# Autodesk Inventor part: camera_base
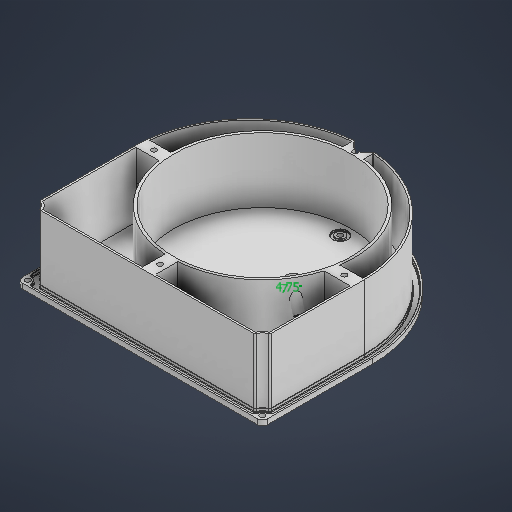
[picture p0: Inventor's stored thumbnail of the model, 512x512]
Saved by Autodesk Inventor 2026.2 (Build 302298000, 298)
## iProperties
Created: 2026-02
Part Number: camera_base
Material: Generic
Document SubType Name: Modeling
Designer: Tathagata Sikdar
Density: 1 g/cm^3
Appearance: Default
Author: Tathagata Sikdar
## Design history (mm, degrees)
sketch "Sketch1"
  geometry: L1 (0, -60.044)-(52, 30.022); L2 (52, 30.022)-(-52, 30.022); L3 (-52, 30.022)-(0, -60.044); L4 (-26, -15.011)-(52, 30.022); L5 (0, -60.044)-(0, 30.022); L6 (94.574, 10.03)-(94.574, 90.574); L7 (-94.574, 10.03)-(-94.574, 90.574); L8 (90.574, 94.574)-(-90.574, 94.574); L9 (93.154, 10.03)-(93.154, 84.168); L10 (84.168, 93.154)-(-84.168, 93.154); L11 (-93.154, 84.168)-(-93.154, 10.03); L12 (88.994, 10.03)-(88.994, 82.391); L13 (82.391, 88.994)-(-82.391, 88.994); L14 (-88.994, 82.391)-(-88.994, 10.03); L15 (-90.574, 90.574)-(-94.574, 94.574); L16 (0, 0)-(90.574, 90.574); L17 (82.089, 87.574)-(-82.089, 87.574); L18 (-87.574, 82.089)-(-87.574, 10.03); L19 (87.574, 10.03)-(87.574, 82.089); L20 (80.971, 87.574)-(56.971, 87.574); L21 (56.971, 87.574)-(56.971, 41.574); L22 (56.971, 41.574)-(80.971, 41.574); L23 (80.971, 41.574)-(80.971, 87.574); L24 (82.391, 40.154)-(55.551, 40.154); L25 (55.551, 40.154)-(55.551, 88.994); L26 (55.551, 88.994)-(82.391, 88.994); L27 (82.391, 88.994)-(82.391, 40.154); C1 r 2 at (0, -60.044); C2 r 2 at (-52, 30.022); C3 r 2 at (52, 30.022); C4 r 5.75 at (52, 30.022); C5 r 3.75 at (52, 30.022); C6 r 3.75 at (-52, 30.022); C7 r 5.75 at (-52, 30.022); C8 r 3.75 at (0, -60.044); C9 r 5.75 at (0, -60.044); C10 r 2 at (-90.574, 90.574); C11 r 2 at (90.574, 90.574); C12 r 2 at (0, -80.544); C13 r 1 at (-92.696, 92.696); A1 r 68.544 centre (0, 0) between (0, -68.544) and (55.551, 40.154); A2 r 94.574 centre (0, 10.03) between (-94.574, 10.03) and (94.574, 10.03); A3 r 3.42 centre (90.574, 90.574) between (87.162, 90.351) and (90.351, 87.162); A4 r 3.42 centre (-90.574, 90.574) between (-90.351, 87.162) and (-87.162, 90.351); A5 r 3.42 centre (0, -80.544) between (3.403, -80.2) and (-3.403, -80.2); A6 r 3 centre (-90.154, 84.168) between (-90.351, 87.162) and (-93.154, 84.168); A7 r 3 centre (-84.168, 90.154) between (-84.168, 93.154) and (-87.162, 90.351); A8 r 3 centre (84.168, 90.154) between (87.162, 90.351) and (84.168, 93.154); A9 r 3 centre (90.154, 84.168) between (93.154, 84.168) and (90.351, 87.162); A10 r 93.154 centre (0, 10.03) between (6.6, -82.89) and (93.154, 10.03); A11 r 93.154 centre (0, 10.03) between (-93.154, 10.03) and (-6.6, -82.89); A12 r 7.58 centre (90.574, 90.574) between (83.345, 88.295) and (88.295, 83.345); A13 r 7.58 centre (-90.574, 90.574) between (-88.295, 83.345) and (-83.345, 88.295); A14 r 88.994 centre (0, 10.03) between (-88.994, 10.03) and (-8.149, -78.591); A15 r 7.58 centre (0, -80.544) between (7.118, -77.939) and (-7.118, -77.939); A16 r 88.994 centre (0, 10.03) between (8.149, -78.591) and (88.994, 10.03); A17 r 1 centre (-87.994, 82.391) between (-88.295, 83.345) and (-88.994, 82.391); A18 r 1 centre (-82.391, 87.994) between (-82.391, 88.994) and (-83.345, 88.295); A19 r 1 centre (82.391, 87.994) between (83.345, 88.295) and (82.391, 88.994); A20 r 1 centre (87.994, 82.391) between (88.994, 82.391) and (88.295, 83.345); A21 r 1 centre (8.057, -77.595) between (7.118, -77.939) and (8.149, -78.591); A22 r 1 centre (-8.057, -77.595) between (-8.149, -78.591) and (-7.118, -77.939); A23 r 3 centre (-6.387, -79.898) between (-6.6, -82.89) and (-3.403, -80.2); A24 r 3 centre (6.387, -79.898) between (3.403, -80.2) and (6.6, -82.89); A25 r 4 centre (90.574, 90.574) between (94.574, 90.574) and (90.574, 94.574); A26 r 4 centre (-90.574, 90.574) between (-90.574, 94.574) and (-94.574, 90.574); A27 r 9 centre (90.574, 90.574) between (82.089, 87.574) and (87.574, 82.089); A28 r 9 centre (-90.574, 90.574) between (-87.574, 82.089) and (-82.089, 87.574); A29 r 87.574 centre (0, 10.03) between (-87.574, 10.03) and (-8.334, -77.147); A30 r 9 centre (0, -80.544) between (8.334, -77.147) and (-8.334, -77.147); A31 r 87.574 centre (0, 10.03) between (8.334, -77.147) and (87.574, 10.03); 9 further points
  constraints: 67 point on circle, 54 end point, 44 centre point, 32 tangent, 20 equal radius, 12 coincident, 9 point on line, 5 concentric, 5 parallel, 4 horizontal, 4 horizontal alignment, 3 midpoint, 3 vertical, 3 vertical alignment, 2 equal length, 2 perpendicular, 22 other
  dimensions: "d0" = 4 diameter of C1; "d1" = 104 distance of L1.end L2.end; "d2" = 6.5 dimension on A1 C2; "d28" = 11.5 diameter of C4; "d29" = 7.5 diameter of C5; "d40" = 4 distance of point (0, -84.544) C12.centre; "d45" = 1.42 distance between parallel lines of L8 L10 (derived); "d47" = 1.42 distance between parallel lines of L6 L9 (derived); "d48" = 1.42 radial gap between concentric circles of A5 C12 (derived); "d49" = 1.42 radial gap between concentric circles of C10 A4 (derived); "d50" = 1.42 radial gap between concentric circles of C11 A3 (derived); "d61" = 4.16 radial gap between concentric circles of A10 A16; "d64" = 1 radius of A17 (derived); "d70" = 4 radius of A25; "d87" = 3 radius of A9; "d90" = 12 distance of C12.centre A1.start; "d109" = 45 deg angle of L8 L15; "d110" = 2 diameter of C13; "d114" = 45 deg angle of L16 L5; "d171" = 1.42 distance from line of point (68.971, 40.154) L22 (derived); "d172" = 46 distance of L20.end L21.end; "d173" = 24 distance of L21.end L22.end
extrude "Extrusion3" new body sketch "Sketch1" distance "d66" = 4; taper "d67" = 0 deg
extrude "Extrusion4" cut sketch "Sketch1" taper "d69" = 0 deg; distance "ORingDepth" = 1.19
extrude "Extrusion5" cut sketch "Sketch1" taper "d72" = 0 deg; distance "FaceSealDepth" = 2.38
fillet "Fillet1" dims "ORingTopRadius" = 0.15
fillet "Fillet2" dims "ORingBottomRadius" = 0.25
fillet "Fillet3" dims "FaceSealBottomRadius" = 0.4
fillet "Fillet4" dims "FaceSealTopRadius" = 0.2
extrude "Extrusion6" join sketch "Sketch1" distance "d115" = 50; taper "d116" = 0 deg
sketch "3D Sketch1" dims "d117" = 7, "d119" = 45 deg
workplane "Work Plane1"
sketch "Sketch2" dims "d120" = 7
  geometry: L1 (-4.583, 1.871)-(0, 0) reference; L2 (0, 0)-(3.24, -1.323); C1 r 2.375 at (3.24, -1.323); 1 further point
  constraints: 2 end point, 1 centre point, 1 coincident, 1 collinear, 3 other
  dimensions: "d121" = 4.75 diameter of C1
extrude "Extrusion7" cut sketch "Sketch2" stored distance "d122" = 50; taper "d123" = 0 deg
extrude "Extrusion10" join sketch "Sketch2" distance "d128" = 7; taper "d130" = 0 deg; dims "d129" = 16, "d131" = 0
sketch "Sketch5"
  geometry: L1 (88.621, 50)-(0, 50) reference; L2 (0, 50)-(-72.362, 50) reference; L3 (-72.362, 50)-(-73.315, 50) reference; L4 (-73.315, 50)-(-78.265, 50) reference; L5 (-78.265, 50)-(-78.964, 50) reference; L6 (-78.964, 50)-(-78.265, 50) reference; L7 (-78.265, 50)-(-73.315, 50) reference; L8 (-73.315, 50)-(-72.362, 50) reference; L9 (-72.362, 50)-(0, 50) reference; L10 (0, 50)-(88.621, 50) reference; L11 (88.621, 50)-(87.969, 50) reference; L12 (87.969, 50)-(87.969, 50) reference; L13 (87.969, 50)-(88.621, 50) reference; L14 (-72.059, 50)-(-77.544, 50) reference; L15 (-77.544, 50)-(-72.059, 50) reference; L16 (-72.059, 50)-(0, 50) reference; L17 (0, 50)-(87.177, 50) reference; L18 (87.177, 50)-(87.177, 50) reference; L19 (87.177, 50)-(0, 50) reference; L20 (0, 50)-(-72.059, 50) reference; L21 (0, 0)-(0, 50) reference; L22 (0, 50)-(10, 50); L23 (10, 50)-(10, 26.34); L24 (10, 26.34)-(5, 35); L25 (0, 50)-(0, 26.34); L26 (0, 26.34)-(5, 35); 2 further points
  constraints: 10 end point, 2 equal length, 2 point on line, 1 perpendicular
  dimensions: "d144" = 10 distance of L1.end L22.end; "d145" = 15 vertical distance of L22.end L24.end; "d148" = 30 deg angle of L25 L26
extrude "Extrusion11" join sketch "Sketch5" stored distance "d146" = 10; taper "d147" = 0 deg
sketch "Sketch6"
  geometry: L1 (-72.059, 50)-(-160.68, 50) reference; L2 (-72.059, 0)-(-72.059, 50) reference; L3 (-72.059, 50)-(-72.059, 26.34); L4 (0.302, 50)-(-72.059, 50) reference; L5 (-72.059, 50)-(-62.059, 50); L6 (-62.059, 50)-(-62.059, 26.34); L7 (-62.059, 26.34)-(-67.059, 35); L8 (-67.059, 35)-(-72.059, 26.34); 1 further point
  constraints: 10 end point, 2 equal length, 2 point on line, 1 vertical
  dimensions: "d149" = 10 distance of L1.start L5.end; "d150" = 15 vertical distance of L5.end L7.end; "d151" = 30 deg angle of L2 L8
extrude "Extrusion12" join sketch "Sketch6" stored distance "d152" = 10; taper "d153" = 0 deg
sketch "Sketch7"
  geometry: L1 (164.481, 50)-(-0.302, 50) reference; L2 (82.089, 0)-(82.089, 50); L3 (82.089, 50)-(77.089, 50); L4 (82.089, 50)-(87.089, 50); L5 (0, 50)-(164.178, 50) reference; L6 (77.089, 50)-(77.089, 26.34); L7 (77.089, 26.34)-(82.089, 35); L8 (82.089, 35)-(87.089, 26.34); L9 (87.089, 26.34)-(87.089, 50); 3 further points
  constraints: 14 end point, 3 point on line, 2 vertical, 1 equal length, 1 midpoint
  dimensions: "d154" = 5 distance of L2.end L3.end; "d155" = 5 distance of L2.end L4.end; "d156" = 30 deg angle of L6 L7; "d157" = 15 distance of L2.end L7.end
extrude "Extrusion13" join sketch "Sketch7" stored distance "d158" = 10; taper "d159" = 0 deg
workplane "Work Plane6"
sketch "Sketch8"
  geometry: L1 (0, 0)-(50, 0) reference; L2 (0, 16.297)-(50, 16.297) reference; L3 (50, 15.267)-(50, 1.031) reference; L4 (50, 15.267)-(50, 16.297) reference; L5 (50, 8.149)-(50, 16.297); L6 (50, 8.149)-(50, 0); L7 (0, 1.031)-(50, 1.031) reference; L8 (50, -80.846)-(50, 0) reference; L9 (50, 0)-(20.886, 0); L10 (20.886, 0)-(35, 8.149); L11 (35, 8.149)-(20.886, 16.297); L12 (20.886, 16.297)-(50, 16.297); 1 further point
  constraints: 12 end point, 2 equal length, 2 point on line, 1 collinear, 1 midpoint, 1 perpendicular, 1 vertical
  dimensions: "d160" = 30 deg angle of L1 L10; "d161" = 15 distance of L5.start L10.end
extrude "Extrusion14" join sketch "Sketch8" stored distance "d162" = 10; taper "d163" = 0 deg
sketch "Sketch9"
  geometry: L1 (-87.432, -5.03)-(-70.348, -5.03) reference; L2 (0, -87.574)-(0, -70.528) reference; L3 (87.574, -15.03)-(68.908, -15.03) reference; A1 r 9 centre (0, 80.544) between (0, 71.544) and (8.149, 76.723) reference; 4 further points
  constraints: 3 midpoint
hole "Hole1" sketch "Sketch9" at (-78.89, -5.03), (0, 71.544), (78.241, -15.03), (0, -79.051) diameter "d164" = 4; stored, may be unused: countersink angle "d168" = 90 deg, drill point angle "d170" = 118 deg; dims "d165" = 6, "d166" = 4, "d167" = 2, "d169" = 14
body "Solid3"
node "Projected Loop5"
other parameters: "d5" = 5, "d7" = 7, "d10" = 4, "d12" = 4, "d14" = 4, "d19" = 2, "d21" = 1.42 (derived), "d22" = 1.42 (derived), "GWThickness" = 1.42, "d91" = 1.42 (derived), "d102" = 3
